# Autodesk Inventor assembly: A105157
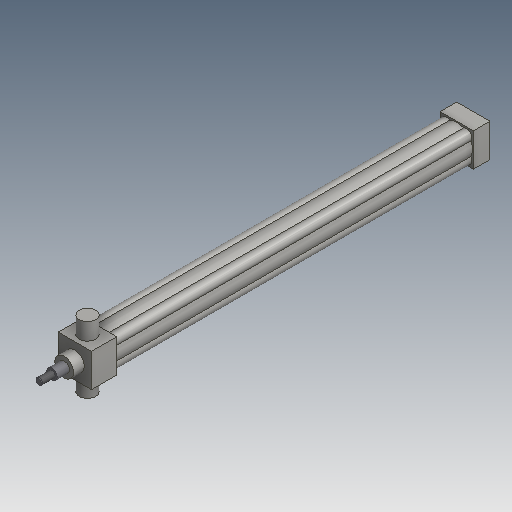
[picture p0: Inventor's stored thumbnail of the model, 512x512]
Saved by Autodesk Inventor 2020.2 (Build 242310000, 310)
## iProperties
Created: 2000-02
Part Number: A105157
Description: CYL,HEAD TRUNION,1.50BX20.00S
Document SubType Name: Assembly
Designer: sspink
Mass: 1900.23 g
Surface Area: 2431.86 cm^2
Volume: 499.546 cm^3
Density: 3.80391 g/cm^3
Control State: 0
Checked Out: False
Master: False
Shininess: 0.0
Length Units: 11269
Angle Units: 11279
Time Units: 11290
Mass Units: 11283
Length Display Precision: 3
Angle Display Precision: 2
Compacted: True
Dimensions: 100x653,9x50 mm
Mass: 1,9 kg
DocNumber: A105157.iam
Folder: 01 - Themengebiete\Simplification\01 - Packaging machine\
VDS_Category: 3D Komponenten
Density: 0.0
Volumn: 0.0
Area: 0.0
PropertySet Name: Model Information
Author: sspink
Revision Number: -
Title: cylinder
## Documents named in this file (3)
- D:\07 - DEMODATEN\OTX 2019 - Dataset - UPDATE - Dez2019\Designs\07-Packing machine\A105157.iam
- D:\07 - DEMODATEN\OTX 2019 - Dataset - UPDATE - Dez2019\Designs\07-Packing machine\Parts\ADSK-011792.ipt
- D:\07 - DEMODATEN\OTX 2019 - Dataset - UPDATE - Dez2019\Designs\07-Packing machine\Parts\ADSK-011793.ipt
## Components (2 placed, 2 different names)
1. ADSK-011792:1 — stroke
2. ADSK-011793:1 — stroke
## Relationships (1: Insert 1)
- stroke [Insert]: ADSK-011792:1 ↔ ADSK-011793:1
